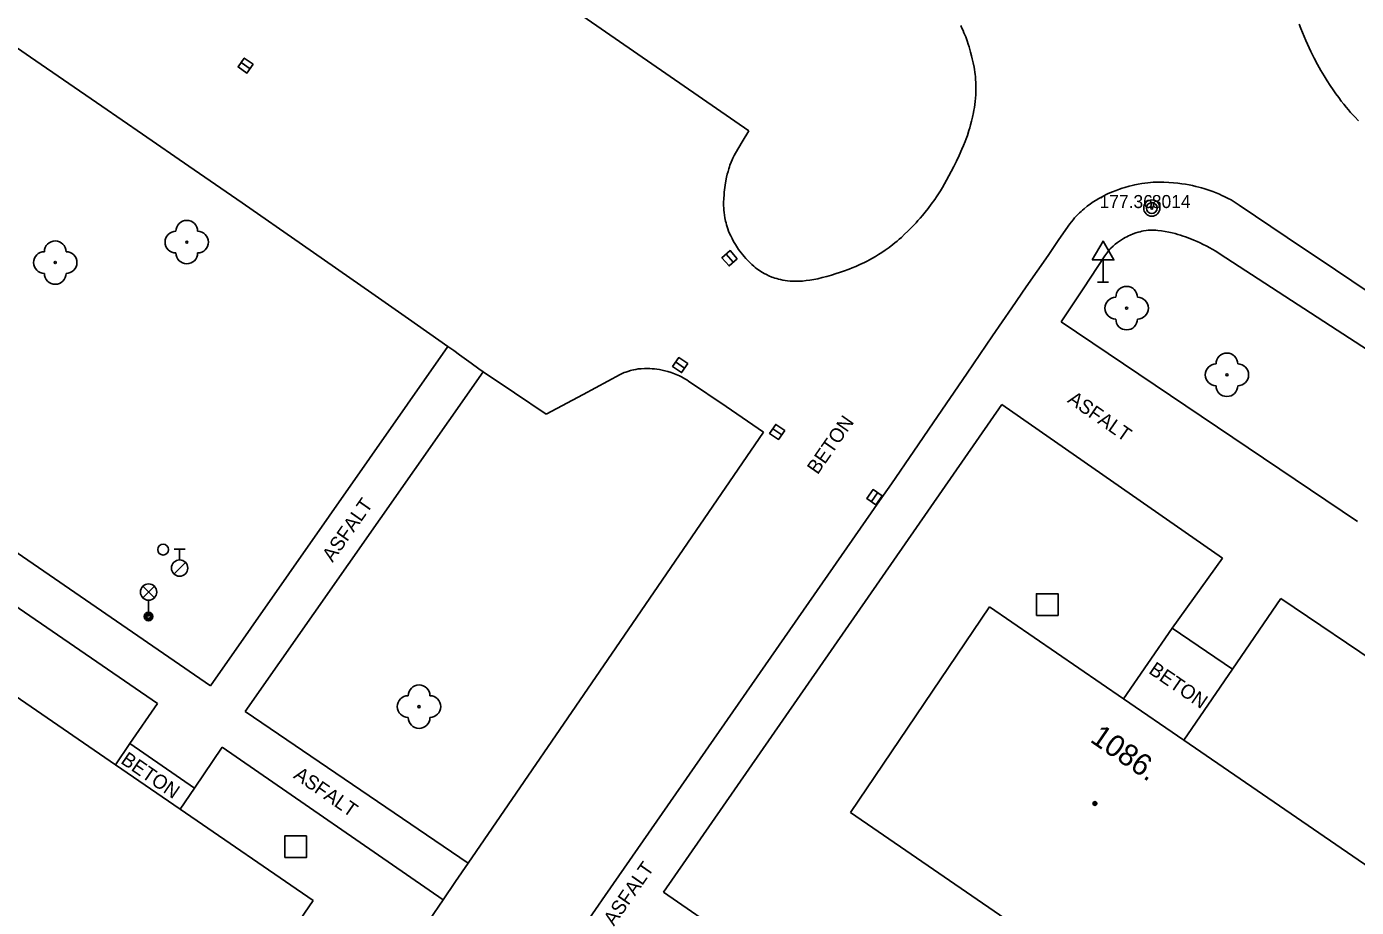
# Model space of a CAD drawing. Extents: x -539515 to -538098, y -1182060 to -1180157.
# Drawn here: x -538972.2 to -538911, y -1181380.9 to -1181340.3 of the extents above; entities that cross this region are included whole.
import ezdxf

# ---------------------------------------------------------------- set-up
doc = ezdxf.new("R2010")
doc.units = 0
for name, color, linetype in [('Vrstva 10', 7, 'Continuous'), ('Vrstva 11', 7, 'Continuous'), ('Vrstva 21', 7, 'Continuous'), ('Vrstva 22', 7, 'Continuous'), ('Vrstva 23', 7, 'Continuous'), ('Vrstva 26', 7, 'Continuous'), ('Vrstva 27', 7, 'Continuous'), ('Vrstva 28', 7, 'Continuous'), ('Vrstva 33', 7, 'Continuous'), ('Vrstva 34', 7, 'Continuous'), ('Vrstva 39', 7, 'Continuous'), ('Vrstva 40', 7, 'Continuous'), ('Vrstva 47', 7, 'Continuous'), ('Vrstva 5', 7, 'Continuous')]:
    doc.layers.add(name, color=color, linetype=linetype)

msp = doc.modelspace()

# ---------------------------------------------------------------- linework, layer by layer
at = {"layer": 'Vrstva 10'}
for p, q in [((-538938.97, -1181345.11), (-538980.87, -1181316.14)), ((-538946.605, -1181357.25), (-538948.31, -1181358.16)), ((-538938.29, -1181358.99), (-538945.095, -1181368.915)), ((-538945.585, -1181380.335), (-538932.95, -1181362.16)), ((-538945.095, -1181368.915), (-538951.9, -1181378.84)), ((-538958.22, -1181398.51), (-538945.585, -1181380.335))]:
    msp.add_line(p, q, dxfattribs=at)
for points in [[(-538966.899, -1181345.268), (-538968.774, -1181343.979), (-538972.058, -1181341.726), (-538974.523, -1181340.041)], [(-538929.204, -1181340.27), (-538929.149, -1181340.384), (-538929.099, -1181340.494), (-538929.054, -1181340.597), (-538928.976, -1181340.793), (-538928.912, -1181340.967), (-538928.86, -1181341.119), (-538928.818, -1181341.254), (-538928.75, -1181341.488), (-538928.704, -1181341.664), (-538928.673, -1181341.794), (-538928.629, -1181341.989), (-538928.59, -1181342.18), (-538928.569, -1181342.294), (-538928.552, -1181342.406), (-538928.538, -1181342.514), (-538928.527, -1181342.62), (-538928.518, -1181342.723), (-538928.506, -1181342.924), (-538928.503, -1181343.113), (-538928.505, -1181343.291), (-538928.513, -1181343.459), (-538928.524, -1181343.617), (-538928.539, -1181343.766), (-538928.556, -1181343.905), (-538928.574, -1181344.036), (-538928.594, -1181344.158), (-538928.615, -1181344.273), (-538928.66, -1181344.488), (-538928.704, -1181344.676), (-538928.747, -1181344.839), (-538928.788, -1181344.982), (-538928.826, -1181345.106), (-538928.898, -1181345.323), (-538928.956, -1181345.484), (-538929.002, -1181345.604), (-538929.074, -1181345.783), (-538929.15, -1181345.96), (-538929.281, -1181346.25), (-538929.405, -1181346.515), (-538929.524, -1181346.759), (-538929.638, -1181346.984)], [(-538913.611, -1181340.195), (-538913.535, -1181340.395), (-538913.459, -1181340.588), (-538913.382, -1181340.775), (-538913.304, -1181340.955), (-538913.227, -1181341.13), (-538913.149, -1181341.299), (-538913.071, -1181341.462), (-538912.994, -1181341.619), (-538912.917, -1181341.771), (-538912.763, -1181342.063), (-538912.611, -1181342.334)], [(-538912.611, -1181342.334), (-538912.463, -1181342.586), (-538912.319, -1181342.818), (-538912.18, -1181343.034), (-538912.045, -1181343.233), (-538911.916, -1181343.417), (-538911.791, -1181343.587), (-538911.672, -1181343.745), (-538911.558, -1181343.891), (-538911.448, -1181344.025), (-538911.344, -1181344.15), (-538911.245, -1181344.265), (-538911.055, -1181344.476), (-538910.885, -1181344.656)], [(-538962.313, -1181348.434), (-538964.758, -1181346.744), (-538966.899, -1181345.268)], [(-538940.123, -1181348.236), (-538940.11, -1181348.06), (-538940.098, -1181347.94), (-538940.084, -1181347.826), (-538940.055, -1181347.611), (-538940.023, -1181347.42), (-538939.99, -1181347.254), (-538939.957, -1181347.108), (-538939.924, -1181346.982), (-538939.892, -1181346.872), (-538939.862, -1181346.777), (-538939.834, -1181346.694), (-538939.781, -1181346.552), (-538939.736, -1181346.447), (-538939.701, -1181346.37), (-538939.644, -1181346.257), (-538939.582, -1181346.146), (-538939.276, -1181345.628), (-538938.97, -1181345.11)], [(-538929.638, -1181346.984), (-538929.747, -1181347.191), (-538929.852, -1181347.382), (-538929.953, -1181347.559), (-538930.05, -1181347.723), (-538930.143, -1181347.875), (-538930.233, -1181348.016), (-538930.32, -1181348.147), (-538930.402, -1181348.269), (-538930.563, -1181348.496), (-538930.71, -1181348.691), (-538930.844, -1181348.861), (-538930.965, -1181349.009), (-538931.075, -1181349.137), (-538931.173, -1181349.249), (-538931.261, -1181349.346), (-538931.421, -1181349.516), (-538931.545, -1181349.642), (-538931.64, -1181349.737), (-538931.788, -1181349.879), (-538931.94, -1181350.02), (-538932.04, -1181350.109), (-538932.138, -1181350.194), (-538932.233, -1181350.273), (-538932.326, -1181350.347), (-538932.507, -1181350.485), (-538932.678, -1181350.608), (-538932.84, -1181350.717), (-538932.993, -1181350.815), (-538933.137, -1181350.902), (-538933.273, -1181350.98), (-538933.401, -1181351.051), (-538933.521, -1181351.114), (-538933.635, -1181351.171), (-538933.848, -1181351.273), (-538934.036, -1181351.356), (-538934.202, -1181351.425), (-538934.347, -1181351.483), (-538934.601, -1181351.577), (-538934.793, -1181351.643), (-538934.937, -1181351.69), (-538935.153, -1181351.757), (-538935.37, -1181351.82), (-538935.58, -1181351.876), (-538935.782, -1181351.923), (-538935.975, -1181351.962), (-538936.158, -1181351.992), (-538936.332, -1181352.014), (-538936.497, -1181352.03), (-538936.652, -1181352.038), (-538936.798, -1181352.041), (-538936.935, -1181352.038), (-538937.064, -1181352.031), (-538937.185, -1181352.019), (-538937.298, -1181352.004), (-538937.404, -1181351.987), (-538937.503, -1181351.967), (-538937.596, -1181351.945)], [(-538925.182, -1181350.848), (-538924.677, -1181350.124), (-538924.17, -1181349.4), (-538924.1, -1181349.304), (-538924.028, -1181349.212), (-538923.955, -1181349.126), (-538923.882, -1181349.045), (-538923.808, -1181348.968), (-538923.735, -1181348.895), (-538923.661, -1181348.826), (-538923.589, -1181348.761), (-538923.516, -1181348.699), (-538923.372, -1181348.584), (-538923.232, -1181348.481), (-538923.096, -1181348.389), (-538922.967, -1181348.306), (-538922.842, -1181348.232), (-538922.724, -1181348.166), (-538922.611, -1181348.107), (-538922.505, -1181348.054), (-538922.404, -1181348.006), (-538922.212, -1181347.922), (-538922.043, -1181347.855), (-538921.895, -1181347.8), (-538921.764, -1181347.756), (-538921.65, -1181347.72), (-538921.45, -1181347.663), (-538921.301, -1181347.626), (-538921.19, -1181347.6), (-538921.024, -1181347.567), (-538920.86, -1181347.54), (-538920.724, -1181347.521), (-538920.59, -1181347.506), (-538920.459, -1181347.495), (-538920.331, -1181347.486), (-538920.205, -1181347.481), (-538920.083, -1181347.478), (-538919.964, -1181347.477), (-538919.848, -1181347.479), (-538919.621, -1181347.488), (-538919.408, -1181347.503), (-538919.207, -1181347.524), (-538919.018, -1181347.548), (-538918.841, -1181347.576), (-538918.675, -1181347.607), (-538918.521, -1181347.639), (-538918.376, -1181347.672), (-538918.241, -1181347.706), (-538918.115, -1181347.74), (-538917.998, -1181347.774), (-538917.78, -1181347.844), (-538917.592, -1181347.911), (-538917.429, -1181347.974), (-538917.289, -1181348.032), (-538917.168, -1181348.086), (-538917.063, -1181348.135), (-538916.883, -1181348.225), (-538916.75, -1181348.297), (-538916.653, -1181348.352), (-538916.51, -1181348.439), (-538916.37, -1181348.53)], [(-538956.336, -1181352.588), (-538959.522, -1181350.37), (-538962.313, -1181348.434)], [(-538937.596, -1181351.945), (-538937.682, -1181351.921), (-538937.763, -1181351.897), (-538937.839, -1181351.872), (-538937.909, -1181351.846), (-538938.041, -1181351.791), (-538938.155, -1181351.738), (-538938.254, -1181351.686), (-538938.34, -1181351.636), (-538938.415, -1181351.59), (-538938.48, -1181351.547), (-538938.592, -1181351.466), (-538938.676, -1181351.401), (-538938.737, -1181351.349), (-538938.829, -1181351.267), (-538938.92, -1181351.18), (-538939.012, -1181351.086), (-538939.097, -1181350.994), (-538939.175, -1181350.906), (-538939.248, -1181350.819), (-538939.316, -1181350.736), (-538939.378, -1181350.654), (-538939.436, -1181350.575), (-538939.49, -1181350.499), (-538939.539, -1181350.424), (-538939.585, -1181350.352), (-538939.669, -1181350.212), (-538939.74, -1181350.08), (-538939.801, -1181349.956), (-538939.853, -1181349.839), (-538939.897, -1181349.73), (-538939.935, -1181349.627), (-538939.967, -1181349.53), (-538939.994, -1181349.439), (-538940.018, -1181349.354), (-538940.037, -1181349.274), (-538940.069, -1181349.123), (-538940.091, -1181348.992), (-538940.106, -1181348.876), (-538940.116, -1181348.774), (-538940.123, -1181348.685), (-538940.129, -1181348.53), (-538940.129, -1181348.412), (-538940.123, -1181348.236)], [(-538916.37, -1181348.53), (-538914.158, -1181350.02), (-538911.945, -1181351.51), (-538909.732, -1181353), (-538907.52, -1181354.49), (-538907.454, -1181354.536), (-538907.393, -1181354.582), (-538907.334, -1181354.628), (-538907.224, -1181354.722), (-538907.126, -1181354.815), (-538907.038, -1181354.907), (-538906.959, -1181354.997), (-538906.887, -1181355.083), (-538906.823, -1181355.167), (-538906.764, -1181355.248), (-538906.711, -1181355.325), (-538906.617, -1181355.474), (-538906.538, -1181355.608), (-538906.473, -1181355.729), (-538906.419, -1181355.836), (-538906.374, -1181355.931)], [(-538930.473, -1181358.564), (-538928.908, -1181356.272), (-538927.734, -1181354.553), (-538926.85, -1181353.264), (-538926.185, -1181352.297), (-538925.182, -1181350.848)], [(-538948.31, -1181358.16), (-538949.755, -1181357.185), (-538951.2, -1181356.21), (-538951.407, -1181356.068), (-538951.764, -1181355.813), (-538952.296, -1181355.425), (-538952.562, -1181355.231), (-538952.83, -1181355.04), (-538954.639, -1181353.773), (-538956.336, -1181352.588)], [(-538938.29, -1181358.99), (-538940.015, -1181357.815), (-538941.74, -1181356.64), (-538941.823, -1181356.585), (-538941.907, -1181356.535), (-538941.989, -1181356.488), (-538942.072, -1181356.444), (-538942.153, -1181356.404), (-538942.233, -1181356.367), (-538942.313, -1181356.333), (-538942.39, -1181356.302), (-538942.544, -1181356.247), (-538942.691, -1181356.201), (-538942.831, -1181356.163), (-538942.964, -1181356.133), (-538943.089, -1181356.109), (-538943.208, -1181356.091), (-538943.319, -1181356.078), (-538943.424, -1181356.068), (-538943.522, -1181356.062), (-538943.613, -1181356.059), (-538943.699, -1181356.059), (-538943.779, -1181356.06), (-538943.928, -1181356.069), (-538944.058, -1181356.082), (-538944.169, -1181356.098), (-538944.266, -1181356.116), (-538944.35, -1181356.135), (-538944.422, -1181356.153), (-538944.546, -1181356.19), (-538944.638, -1181356.222), (-538944.705, -1181356.248), (-538944.804, -1181356.292), (-538944.9, -1181356.34), (-538946.605, -1181357.25)], [(-538932.95, -1181362.16), (-538932.399, -1181361.365), (-538931.37, -1181359.872), (-538930.473, -1181358.564)], [(-538951.9, -1181378.84), (-538952.475, -1181379.685), (-538953.05, -1181380.53), (-538953.68, -1181381.448), (-538954.867, -1181383.164), (-538955.91, -1181384.663), (-538956.826, -1181385.973)]]:
    msp.add_lwpolyline(points, dxfattribs=at)
at = {"layer": 'Vrstva 11'}
for p, q in [((-538993.14, -1181350.51), (-538963.76, -1181370.67)), ((-538917.3, -1181350.76), (-538912.17, -1181354.09)), ((-538924.57, -1181353.91), (-538910.92, -1181363.1)), ((-538912.17, -1181354.09), (-538907.04, -1181357.42)), ((-538963.76, -1181370.67), (-538952.83, -1181355.04)), ((-538951.2, -1181356.21), (-538962.17, -1181371.85)), ((-538927.31, -1181357.71), (-538942.9, -1181380.17)), ((-538917.14, -1181364.8), (-538927.31, -1181357.71)), ((-538966.21, -1181371.48), (-538978.15, -1181363.3)), ((-538919.46, -1181368.01), (-538917.14, -1181364.8)), ((-538914.45, -1181366.65), (-538916.687, -1181369.912)), ((-538902.2, -1181374.93), (-538914.45, -1181366.65)), ((-538921.702, -1181371.278), (-538919.46, -1181368.01)), ((-538916.687, -1181369.912), (-538919.46, -1181368.01)), ((-538918.929, -1181373.18), (-538916.687, -1181369.912)), ((-538967.482, -1181373.333), (-538966.21, -1181371.48)), ((-538962.17, -1181371.85), (-538951.9, -1181378.84)), ((-538968.151, -1181374.308), (-538967.482, -1181373.333)), ((-538967.482, -1181373.333), (-538964.5, -1181375.38)), ((-538963.23, -1181373.5), (-538964.5, -1181375.38)), ((-538953.05, -1181380.53), (-538963.23, -1181373.5)), ((-538965.169, -1181376.355), (-538964.5, -1181375.38)), ((-538942.9, -1181380.17), (-538929.62, -1181389.3))]:
    msp.add_line(p, q, dxfattribs=at)
msp.add_lwpolyline([(-538924.57, -1181353.91), (-538923.57, -1181352.39), (-538922.57, -1181350.87), (-538922.525, -1181350.804), (-538922.478, -1181350.741), (-538922.43, -1181350.682), (-538922.381, -1181350.625), (-538922.332, -1181350.571), (-538922.282, -1181350.52), (-538922.182, -1181350.425), (-538922.082, -1181350.339), (-538921.984, -1181350.263), (-538921.889, -1181350.195), (-538921.797, -1181350.134), (-538921.709, -1181350.08), (-538921.624, -1181350.032), (-538921.544, -1181349.99), (-538921.468, -1181349.952), (-538921.396, -1181349.919), (-538921.26, -1181349.863), (-538921.139, -1181349.819), (-538921.034, -1181349.785), (-538920.941, -1181349.76), (-538920.86, -1181349.741), (-538920.79, -1181349.726), (-538920.667, -1181349.706), (-538920.576, -1181349.696), (-538920.508, -1181349.691), (-538920.408, -1181349.688), (-538920.31, -1181349.69), (-538920.217, -1181349.696), (-538920.126, -1181349.704), (-538919.948, -1181349.725), (-538919.779, -1181349.751), (-538919.62, -1181349.782), (-538919.47, -1181349.815), (-538919.329, -1181349.85), (-538919.196, -1181349.887), (-538919.072, -1181349.924), (-538918.956, -1181349.962), (-538918.847, -1181349.999), (-538918.643, -1181350.074), (-538918.466, -1181350.145), (-538918.313, -1181350.211), (-538918.18, -1181350.272), (-538918.065, -1181350.327), (-538917.867, -1181350.428), (-538917.721, -1181350.507), (-538917.613, -1181350.568), (-538917.454, -1181350.663), (-538917.3, -1181350.76)], dxfattribs=at)
at = {"layer": 'Vrstva 21'}
for radius in [0.375, 0.05]:
    msp.add_circle((-538920.4, -1181348.67), radius, dxfattribs=at)
at = {"layer": 'Vrstva 22'}
for centre in [(-538964.86, -1181350.24), (-538970.92, -1181351.18), (-538921.56, -1181353.28), (-538916.94, -1181356.35), (-538954.16, -1181371.63)]:
    msp.add_circle(centre, 0.05, dxfattribs=at)
for centre, start, end in [((-538964.86, -1181349.74), 0, 180), ((-538970.92, -1181350.68), 0, 180), ((-538965.36, -1181350.24), 90, 270), ((-538964.36, -1181350.24), 270, 90), ((-538971.42, -1181351.18), 90, 270), ((-538970.42, -1181351.18), 270, 90), ((-538964.86, -1181350.74), 180, 0), ((-538970.92, -1181351.68), 180, 0), ((-538921.56, -1181352.78), 0, 180), ((-538922.06, -1181353.28), 90, 270), ((-538921.06, -1181353.28), 270, 90), ((-538921.56, -1181353.78), 180, 0), ((-538916.94, -1181355.85), 0, 180), ((-538917.44, -1181356.35), 90, 270), ((-538916.44, -1181356.35), 270, 90), ((-538916.94, -1181356.85), 180, 0), ((-538954.66, -1181371.63), 90, 270), ((-538954.16, -1181371.13), 0, 180), ((-538953.66, -1181371.63), 270, 90), ((-538954.16, -1181372.13), 180, 0)]:
    msp.add_arc(centre, 0.5, start, end, dxfattribs=at)
at = {"layer": 'Vrstva 26'}
for points in [[(-538925.72, -1181367.43), (-538924.72, -1181367.43), (-538924.72, -1181366.43), (-538925.72, -1181366.43)], [(-538960.35, -1181378.58), (-538959.35, -1181378.58), (-538959.35, -1181377.58), (-538960.35, -1181377.58)]]:
    msp.add_lwpolyline(points, close=True, dxfattribs=at)
at = {"layer": 'Vrstva 27'}
for p, q in [((-538961.944, -1181342.252), (-538962.356, -1181341.968)), ((-538939.686, -1181351.168), (-538940.014, -1181350.792)), ((-538941.923, -1181356.041), (-538942.337, -1181355.759)), ((-538937.453, -1181359.121), (-538937.867, -1181358.839)), ((-538933.322, -1181362.189), (-538933.036, -1181361.779))]:
    msp.add_line(p, q, dxfattribs=at)
for points in [[(-538961.802, -1181342.046), (-538962.214, -1181341.762), (-538962.498, -1181342.174), (-538962.086, -1181342.458)], [(-538939.497, -1181351.004), (-538939.826, -1181350.627), (-538940.203, -1181350.956), (-538939.874, -1181351.333)], [(-538941.783, -1181355.834), (-538942.196, -1181355.553), (-538942.477, -1181355.966), (-538942.064, -1181356.247)], [(-538937.313, -1181358.914), (-538937.726, -1181358.633), (-538938.007, -1181359.046), (-538937.594, -1181359.327)], [(-538933.116, -1181362.332), (-538932.831, -1181361.921), (-538933.242, -1181361.636), (-538933.527, -1181362.047)]]:
    msp.add_lwpolyline(points, close=True, dxfattribs=at)
at = {"layer": 'Vrstva 28'}
for p, q in [((-538965.44, -1181364.375), (-538964.94, -1181364.375)), ((-538965.19, -1181364.875), (-538965.19, -1181364.375)), ((-538965.448, -1181365.522), (-538964.918, -1181364.992))]:
    msp.add_line(p, q, dxfattribs=at)
for centre, radius in [((-538920.4, -1181348.67), 0.25), ((-538965.95, -1181364.4), 0.25), ((-538965.19, -1181365.25), 0.375)]:
    msp.add_circle(centre, radius, dxfattribs=at)
at = {"layer": 'Vrstva 33'}
for p, q in [((-538966.885, -1181366.62), (-538966.355, -1181366.09)), ((-538966.885, -1181366.09), (-538966.355, -1181366.62)), ((-538966.62, -1181366.73), (-538966.62, -1181367.48))]:
    msp.add_line(p, q, dxfattribs=at)
for centre, radius in [((-538966.62, -1181366.355), 0.375), ((-538966.62, -1181367.48), 0.2), ((-538966.62, -1181367.48), 0.145), ((-538966.62, -1181367.48), 0.0876)]:
    msp.add_circle(centre, radius, dxfattribs=at)
at = {"layer": 'Vrstva 34'}
for p, q in [((-538922.646, -1181351.06), (-538922.646, -1181352.078)), ((-538922.896, -1181352.078), (-538922.396, -1181352.078))]:
    msp.add_line(p, q, dxfattribs=at)
msp.add_lwpolyline([(-538923.146, -1181351.06), (-538922.146, -1181351.06), (-538922.646, -1181350.194)], close=True, dxfattribs=at)
at = {"layer": 'Vrstva 39'}
for radius in [0.09, 0.0398]:
    msp.add_circle((-538923.021, -1181376.09), radius, dxfattribs=at)
at = {"layer": 'Vrstva 5'}
for p, q in [((-538927.88, -1181367.04), (-538934.28, -1181376.5)), ((-538934.28, -1181376.5), (-538829.84, -1181448.24)), ((-538965.51, -1181389.96), (-538959.04, -1181380.56))]:
    msp.add_line(p, q, dxfattribs=at)
for points in [[(-538968.151, -1181374.308), (-538980.067, -1181366.132)], [(-538823.35, -1181438.74), (-538829.489, -1181434.529), (-538832.387, -1181432.541), (-538844.312, -1181424.362), (-538847.204, -1181422.378), (-538859.26, -1181414.108), (-538862.116, -1181412.15), (-538874.006, -1181403.993), (-538876.874, -1181402.026), (-538889.05, -1181393.675), (-538892.015, -1181391.641), (-538903.87, -1181383.509), (-538906.736, -1181381.543), (-538918.929, -1181373.18), (-538921.702, -1181371.278), (-538927.88, -1181367.04)], [(-538965.169, -1181376.355), (-538968.151, -1181374.308)], [(-538959.04, -1181380.56), (-538965.169, -1181376.355)]]:
    msp.add_lwpolyline(points, dxfattribs=at)

# ---------------------------------------------------------------- texts
at = {"layer": 'Vrstva 22'}
msp.add_text('177.36 ', height=0.6, dxfattribs=at).set_placement((-538922.807, -1181348.67))
at = {"layer": 'Vrstva 23'}
msp.add_text('8014', height=0.6, dxfattribs=at).set_placement((-538920.4, -1181348.67))
at = {"layer": 'Vrstva 40'}
for s, rotation, p in [('ASFALT', 325.11778, (-538924.326, -1181357.587)), ('BETON', 55.19495, (-538935.799, -1181360.978)), ('ASFALT', 54.95393, (-538958.143, -1181365.016)), ('BETON', 325.5527, (-538920.587, -1181370.063)), ('BETON', 325.5426, (-538967.944, -1181374.207)), ('ASFALT', 325.37222, (-538959.985, -1181374.888)), ('ASFALT', 55.19376, (-538945.181, -1181381.767))]:
    msp.add_text(s, height=0.65, rotation=rotation, dxfattribs=at).set_placement(p)
at = {"layer": 'Vrstva 47'}
msp.add_text('1086.', height=1, rotation=325.5527, dxfattribs=at).set_placement((-538923.294, -1181373.217))

doc.saveas('drawing.dxf')
